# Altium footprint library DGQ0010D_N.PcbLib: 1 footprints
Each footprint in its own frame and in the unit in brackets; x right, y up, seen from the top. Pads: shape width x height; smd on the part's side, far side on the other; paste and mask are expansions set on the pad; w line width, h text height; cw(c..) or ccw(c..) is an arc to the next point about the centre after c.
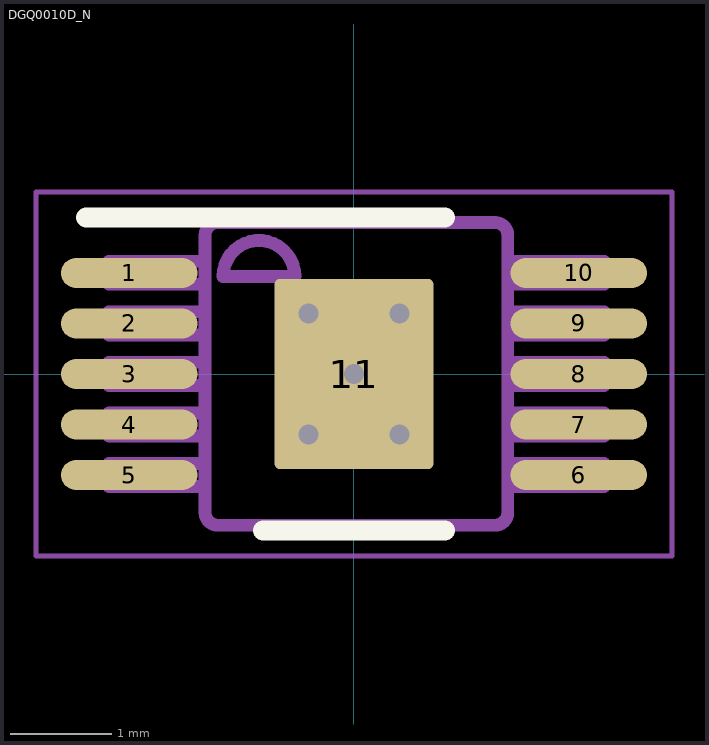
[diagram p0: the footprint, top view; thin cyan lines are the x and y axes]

## DGQ0010D_N [mm] "TSSOP, 10-Leads, Body 3x3mm, Pitch 0.5mm, Thermal Pad 1.88x1.57mm, IPC Medium Density"
height 1.1
pads (11):
  rrect100% 1.35x0.3 smd: 1(-2.225,1) 2(-2.225,0.5) 3(-2.225,0) 4(-2.225,-0.5) 5(-2.225,-1) 6(2.225,-1) 7(2.225,-0.5) 8(2.225,0) 9(2.225,0.5) 10(2.225,1)
  rrect6% 1.57x1.88 smd: 11(0,0)
via -0.45,0.6 diameter 0.5 hole 0.2
via -0.45,-0.6 diameter 0.5 hole 0.2
via 0.45,-0.6 diameter 0.5 hole 0.2
via 0.45,0.6 diameter 0.5 hole 0.2
via 0,0 diameter 0.5 hole 0.2
Top Overlay:
  lines w0.2: -2.65,1.55 0.9,1.55 ; -0.9,-1.55 0.9,-1.55
M5 Assembly Top:
  lines w0.127: -2.427,-1.114 -2.187,-1.114 -2.067,-1.114 -2.064,-1.114 -1.76,-1.114 -1.474,-1.114 -1.474,-0.885 -1.76,-0.885 -2.064,-0.885 -2.067,-0.885 -2.187,-0.885 -2.427,-0.885 -2.427,-1.114 ; -2.427,-0.613 -2.187,-0.613 -2.067,-0.613 -2.064,-0.613 -1.76,-0.613 -1.474,-0.613 -1.474,-0.385 -1.76,-0.385 -2.064,-0.385 -2.067,-0.385 -2.187,-0.385 -2.427,-0.385 -2.427,-0.613 ; -2.427,-0.113 -2.187,-0.113 -2.067,-0.113 -2.064,-0.113 -1.76,-0.113 -1.474,-0.113 -1.474,0.116 -1.76,0.116 -2.064,0.116 -2.067,0.116 -2.187,0.116 -2.427,0.116 -2.427,-0.113 ; -2.427,0.388 -2.187,0.388 -2.067,0.388 -2.064,0.388 -1.76,0.388 -1.474,0.388 -1.474,0.616 -1.76,0.616 -2.064,0.616 -2.067,0.616 -2.187,0.616 -2.427,0.616 -2.427,0.388 ; -2.427,0.888 -2.187,0.888 -2.067,0.888 -2.064,0.888 -1.76,0.888 -1.474,0.888 -1.474,1.116 -1.76,1.116 -2.064,1.116 -2.067,1.116 -2.187,1.116 -2.427,1.116 -2.427,0.888 ; -1.474,-1.373 ccw(c-1.347,-1.37) -1.35,-1.497 -1.347,-1.497 1.396,-1.497 1.399,-1.497 ccw(c1.396,-1.37) 1.523,-1.373 1.523,-1.37 1.523,1.373 1.523,1.376 ccw(c1.396,1.373) 1.399,1.5 1.396,1.5 -1.347,1.5 -1.35,1.5 ccw(c-1.347,1.373) -1.474,1.376 -1.474,1.373 -1.474,-1.37 -1.474,-1.373 ; -1.296,0.967 cw(c-0.941,0.967) -0.585,0.967 -1.296,0.967 ; 1.523,-1.114 1.523,-0.885 1.809,-0.885 2.113,-0.885 2.116,-0.885 2.236,-0.885 2.475,-0.885 2.475,-1.114 2.236,-1.114 2.116,-1.114 2.113,-1.114 1.809,-1.114 1.523,-1.114 ; 1.523,-0.613 1.523,-0.385 1.809,-0.385 2.113,-0.385 2.116,-0.385 2.236,-0.385 2.475,-0.385 2.475,-0.613 2.236,-0.613 2.116,-0.613 2.113,-0.613 1.809,-0.613 1.523,-0.613 ; 1.523,-0.113 1.523,0.116 1.809,0.116 2.113,0.116 2.116,0.116 2.236,0.116 2.475,0.116 2.475,-0.113 2.236,-0.113 2.116,-0.113 2.113,-0.113 1.809,-0.113 1.523,-0.113 ; 1.523,0.388 1.523,0.616 1.809,0.616 2.113,0.616 2.116,0.616 2.236,0.616 2.475,0.616 2.475,0.388 2.236,0.388 2.116,0.388 2.113,0.388 1.809,0.388 1.523,0.388 ; 1.523,0.888 1.523,1.116 1.809,1.116 2.113,1.116 2.116,1.116 2.236,1.116 2.475,1.116 2.475,0.888 2.236,0.888 2.116,0.888 2.113,0.888 1.809,0.888 1.523,0.888
  text ".Designator" at -0.975,-0.25 h0.51
M15 Courtyards Top:
  lines w0.05: -3.15,-1.8 -3.15,1.8 3.15,1.8 3.15,-1.8 -3.15,-1.8
  lines w0.1: -0.5,0 0.5,0 ; 0,-0.5 0,0.5
3D body: height 1.1, standoff 0, extent -2.46,-1.5 2.46,1.5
